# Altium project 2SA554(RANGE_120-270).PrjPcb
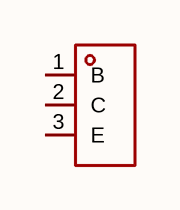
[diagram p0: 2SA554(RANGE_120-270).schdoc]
1 sheet, 1 parts. Net scope: global (net labels, ports and power ports of the same name join across sheets).

## Sheet 2SA554(RANGE_120-270).schdoc
size 127 x 101 mm

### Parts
Q?  2sa554(range:120-270)  [SOT-89-3_L4.5-W2.5-P1.50-LS4.2-BR]  (value not drawn)

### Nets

Not connected (* = marked no-connect by the designer): Q? 1(B) 2(C) 3(E)

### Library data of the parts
Q? = 2sa554(range:120-270): 晶体管类型:PNP;集电极电流(Ic):2A;集射极击穿电压(Vceo):100V;耗散功率(Pd):500mW;直流电流增益(hFE):270;; Manufacturer: CJ(江苏长电/长晶); AddInBom: yes; ModelId: 6db690b7897d4d18a30d90c1b89525ee; ModelName: SOT-89-3_L4.3-W2.5-H1.6-LS4.1-P1.50; ModelTransform: 161.417,169.291,0,180,0,0,-18.661,0,0; type: PNP; Current - Collector(Ic): 2A; Collector - Emitter Voltage VCEO: 100V; Pd - Power Dissipation: 500mW; DC Current Gain: 270; Transition frequency(fT): 30MHz; Current - Collector Cutoff: 1uA; Vce Saturation(VCE(sat)): 300mV; Emitter-Base Voltage(Vebo): 6V; Number: 1个PNP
